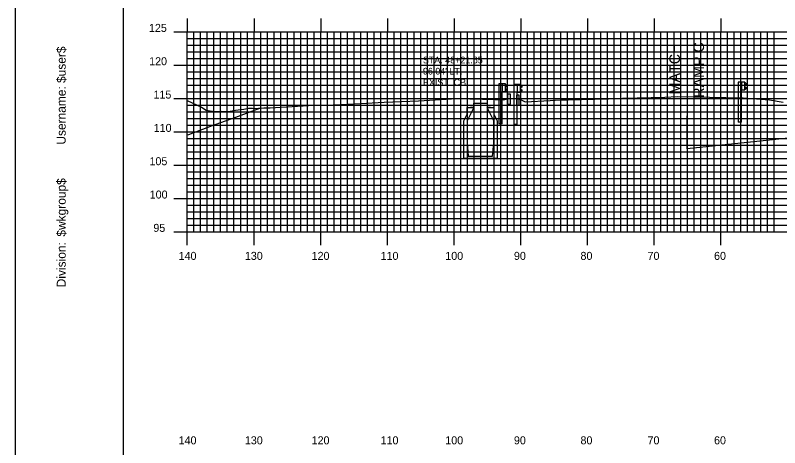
# Model space of a CAD drawing. Extents: x 1754708 to 1755051, y 442591 to 442811.
# Drawn here: x 1754707.7 to 1754822.3, y 442654.9 to 442719.8 of the extents above; entities that cross this region are included whole.
import ezdxf

# ---------------------------------------------------------------- set-up
doc = ezdxf.new("R2010")
doc.units = 0
for name, color, linetype in [('ANNOTATION', 7, 'Continuous'), ('BORDER', 7, 'Continuous'), ('D_Roadway_SlopeLines', 7, 'Continuous'), ('D_Roadway_SubGrade', 7, 'Continuous'), ('D_Text_Monospaced', 7, 'Continuous'), ('H_V ANNOTATION', 7, 'Continuous'), ('M_Roadway_Centerline', 7, 'Continuous'), ('MAJOR', 7, 'Continuous'), ('MINOR', 7, 'Continuous'), ('PLOT BOUNDARY', 7, 'Continuous'), ('S_Curb_Type_1', 7, 'Continuous'), ('S_Drainage_CB', 7, 'Continuous'), ('S_Guardrail_Beam', 7, 'Continuous'), ('S_Roadway_Centerline', 7, 'Continuous')]:
    doc.layers.add(name, color=color, linetype=linetype)

msp = doc.modelspace()

# ---------------------------------------------------------------- linework, layer by layer
at = {"layer": 'BORDER'}
msp.add_lwpolyline([(1754723.92, 442596.67), (1755043.92, 442596.67), (1755043.92, 442806.67), (1754723.92, 442806.67)], close=True, dxfattribs=at)
at = {"layer": 'D_Roadway_SlopeLines'}
for p, q in [((1754808.44, 442699.79), (1754808.44, 442704.73)), ((1754839.49, 442702.99), (1754808.44, 442699.79))]:
    msp.add_line(p, q, dxfattribs=at)
at = {"layer": 'D_Roadway_SubGrade'}
msp.add_line((1754808.44, 442716.86), (1754808.44, 442699.79), dxfattribs=at)
at = {"layer": 'MAJOR'}
for p, q in [((1754733.52, 442719.32), (1754733.52, 442717.31)), ((1754743.52, 442719.32), (1754743.52, 442717.31)), ((1754753.52, 442719.32), (1754753.52, 442717.31)), ((1754763.52, 442719.32), (1754763.52, 442717.31)), ((1754773.52, 442719.32), (1754773.52, 442717.31)), ((1754783.52, 442719.32), (1754783.52, 442717.31)), ((1754793.52, 442719.32), (1754793.52, 442717.31)), ((1754803.52, 442719.32), (1754803.52, 442717.31)), ((1754813.52, 442719.32), (1754813.52, 442717.31)), ((1754731.51, 442717.31), (1754733.52, 442717.31)), ((1754733.52, 442717.31), (1755013.52, 442717.31)), ((1754733.52, 442687.31), (1754733.52, 442717.31)), ((1754733.52, 442687.31), (1754733.52, 442717.31)), ((1754733.52, 442717.31), (1755013.52, 442717.31)), ((1754743.52, 442687.31), (1754743.52, 442717.31)), ((1754753.52, 442687.31), (1754753.52, 442717.31)), ((1754763.52, 442687.31), (1754763.52, 442717.31)), ((1754773.52, 442687.31), (1754773.52, 442717.31)), ((1754783.52, 442687.31), (1754783.52, 442717.31)), ((1754793.52, 442687.31), (1754793.52, 442717.31)), ((1754803.52, 442687.31), (1754803.52, 442717.31)), ((1754813.52, 442687.31), (1754813.52, 442717.31)), ((1754731.51, 442712.31), (1754733.52, 442712.31)), ((1754733.52, 442712.31), (1755013.52, 442712.31)), ((1754731.51, 442707.31), (1754733.52, 442707.31)), ((1754733.52, 442707.31), (1755013.52, 442707.31)), ((1754731.51, 442702.31), (1754733.52, 442702.31)), ((1754733.52, 442702.31), (1755013.52, 442702.31)), ((1754731.51, 442697.31), (1754733.52, 442697.31)), ((1754733.52, 442697.31), (1755013.52, 442697.31)), ((1754731.51, 442692.31), (1754733.52, 442692.31)), ((1754733.52, 442692.31), (1755013.52, 442692.31)), ((1754731.51, 442687.31), (1754733.52, 442687.31)), ((1754733.52, 442687.31), (1755013.52, 442687.31)), ((1754733.52, 442687.31), (1755013.52, 442687.31)), ((1754733.52, 442685.31), (1754733.52, 442687.31)), ((1754743.52, 442685.31), (1754743.52, 442687.31)), ((1754753.52, 442685.31), (1754753.52, 442687.31)), ((1754763.52, 442685.31), (1754763.52, 442687.31)), ((1754773.52, 442685.31), (1754773.52, 442687.31)), ((1754783.52, 442685.31), (1754783.52, 442687.31)), ((1754793.52, 442685.31), (1754793.52, 442687.31)), ((1754803.52, 442685.31), (1754803.52, 442687.31)), ((1754813.52, 442685.31), (1754813.52, 442687.31))]:
    msp.add_line(p, q, dxfattribs=at)
at = {"layer": 'MINOR'}
for p, q in [((1754734.52, 442687.31), (1754734.52, 442717.31)), ((1754735.52, 442687.31), (1754735.52, 442717.31)), ((1754736.52, 442687.31), (1754736.52, 442717.31)), ((1754737.52, 442687.31), (1754737.52, 442717.31)), ((1754738.52, 442687.31), (1754738.52, 442717.31)), ((1754739.52, 442687.31), (1754739.52, 442717.31)), ((1754740.52, 442687.31), (1754740.52, 442717.31)), ((1754741.52, 442687.31), (1754741.52, 442717.31)), ((1754742.52, 442687.31), (1754742.52, 442717.31)), ((1754744.52, 442687.31), (1754744.52, 442717.31)), ((1754745.52, 442687.31), (1754745.52, 442717.31)), ((1754746.52, 442687.31), (1754746.52, 442717.31)), ((1754747.52, 442687.31), (1754747.52, 442717.31)), ((1754748.52, 442687.31), (1754748.52, 442717.31)), ((1754749.52, 442687.31), (1754749.52, 442717.31)), ((1754750.52, 442687.31), (1754750.52, 442717.31)), ((1754751.52, 442687.31), (1754751.52, 442717.31)), ((1754752.52, 442687.31), (1754752.52, 442717.31)), ((1754754.52, 442687.31), (1754754.52, 442717.31)), ((1754755.52, 442687.31), (1754755.52, 442717.31)), ((1754756.52, 442687.31), (1754756.52, 442717.31)), ((1754757.52, 442687.31), (1754757.52, 442717.31)), ((1754758.52, 442687.31), (1754758.52, 442717.31)), ((1754759.52, 442687.31), (1754759.52, 442717.31)), ((1754760.52, 442687.31), (1754760.52, 442717.31)), ((1754761.52, 442687.31), (1754761.52, 442717.31)), ((1754762.52, 442687.31), (1754762.52, 442717.31)), ((1754764.52, 442687.31), (1754764.52, 442717.31)), ((1754765.52, 442687.31), (1754765.52, 442717.31)), ((1754766.52, 442687.31), (1754766.52, 442717.31)), ((1754767.52, 442687.31), (1754767.52, 442717.31)), ((1754768.52, 442687.31), (1754768.52, 442717.31)), ((1754769.52, 442687.31), (1754769.52, 442717.31)), ((1754770.52, 442687.31), (1754770.52, 442717.31)), ((1754771.52, 442687.31), (1754771.52, 442717.31)), ((1754772.52, 442687.31), (1754772.52, 442717.31)), ((1754774.52, 442687.31), (1754774.52, 442717.31)), ((1754775.52, 442687.31), (1754775.52, 442717.31)), ((1754776.52, 442687.31), (1754776.52, 442717.31)), ((1754777.52, 442687.31), (1754777.52, 442717.31)), ((1754778.52, 442687.31), (1754778.52, 442717.31)), ((1754779.52, 442687.31), (1754779.52, 442717.31)), ((1754780.52, 442687.31), (1754780.52, 442717.31)), ((1754781.52, 442687.31), (1754781.52, 442717.31)), ((1754782.52, 442687.31), (1754782.52, 442717.31)), ((1754784.52, 442687.31), (1754784.52, 442717.31)), ((1754785.52, 442687.31), (1754785.52, 442717.31)), ((1754786.52, 442687.31), (1754786.52, 442717.31)), ((1754787.52, 442687.31), (1754787.52, 442717.31)), ((1754788.52, 442687.31), (1754788.52, 442717.31)), ((1754789.52, 442687.31), (1754789.52, 442717.31)), ((1754790.52, 442687.31), (1754790.52, 442717.31)), ((1754791.52, 442687.31), (1754791.52, 442717.31)), ((1754792.52, 442687.31), (1754792.52, 442717.31)), ((1754794.52, 442687.31), (1754794.52, 442717.31)), ((1754795.52, 442687.31), (1754795.52, 442717.31)), ((1754796.52, 442687.31), (1754796.52, 442717.31)), ((1754797.52, 442687.31), (1754797.52, 442717.31)), ((1754798.52, 442687.31), (1754798.52, 442717.31)), ((1754799.52, 442687.31), (1754799.52, 442717.31)), ((1754800.52, 442687.31), (1754800.52, 442717.31)), ((1754801.52, 442687.31), (1754801.52, 442717.31)), ((1754802.52, 442687.31), (1754802.52, 442717.31)), ((1754804.52, 442687.31), (1754804.52, 442717.31)), ((1754805.52, 442687.31), (1754805.52, 442717.31)), ((1754806.52, 442687.31), (1754806.52, 442717.31)), ((1754807.52, 442687.31), (1754807.52, 442717.31)), ((1754808.52, 442687.31), (1754808.52, 442717.31)), ((1754809.52, 442687.31), (1754809.52, 442717.31)), ((1754810.52, 442687.31), (1754810.52, 442717.31)), ((1754811.52, 442687.31), (1754811.52, 442717.31)), ((1754812.52, 442687.31), (1754812.52, 442717.31)), ((1754814.52, 442687.31), (1754814.52, 442717.31)), ((1754815.52, 442687.31), (1754815.52, 442717.31)), ((1754816.52, 442687.31), (1754816.52, 442717.31)), ((1754817.52, 442687.31), (1754817.52, 442717.31)), ((1754818.52, 442687.31), (1754818.52, 442717.31)), ((1754819.52, 442687.31), (1754819.52, 442717.31)), ((1754820.52, 442687.31), (1754820.52, 442717.31)), ((1754821.52, 442687.31), (1754821.52, 442717.31)), ((1754733.52, 442716.31), (1755013.52, 442716.31)), ((1754733.52, 442716.31), (1754735.52, 442716.31)), ((1754733.52, 442715.31), (1755013.52, 442715.31)), ((1754733.52, 442715.31), (1754735.52, 442715.31)), ((1754733.52, 442714.31), (1755013.52, 442714.31)), ((1754733.52, 442714.31), (1754735.52, 442714.31)), ((1754733.52, 442713.31), (1755013.52, 442713.31)), ((1754733.52, 442713.31), (1754735.52, 442713.31)), ((1754733.52, 442711.31), (1755013.52, 442711.31)), ((1754733.52, 442711.31), (1754735.52, 442711.31)), ((1754733.52, 442710.31), (1755013.52, 442710.31)), ((1754733.52, 442710.31), (1754735.52, 442710.31)), ((1754733.52, 442709.31), (1755013.52, 442709.31)), ((1754733.52, 442709.31), (1754735.52, 442709.31)), ((1754733.52, 442708.31), (1755013.52, 442708.31)), ((1754733.52, 442708.31), (1754735.52, 442708.31)), ((1754733.52, 442706.31), (1755013.52, 442706.31)), ((1754733.52, 442706.31), (1754735.52, 442706.31)), ((1754733.52, 442705.31), (1755013.52, 442705.31)), ((1754733.52, 442705.31), (1754735.52, 442705.31)), ((1754733.52, 442704.31), (1755013.52, 442704.31)), ((1754733.52, 442704.31), (1754735.52, 442704.31)), ((1754733.52, 442703.31), (1755013.52, 442703.31)), ((1754733.52, 442703.31), (1754735.52, 442703.31)), ((1754733.52, 442701.31), (1755013.52, 442701.31)), ((1754733.52, 442701.31), (1754735.52, 442701.31)), ((1754733.52, 442700.31), (1755013.52, 442700.31)), ((1754733.52, 442700.31), (1754735.52, 442700.31)), ((1754733.52, 442699.31), (1755013.52, 442699.31)), ((1754733.52, 442699.31), (1754735.52, 442699.31)), ((1754733.52, 442698.31), (1755013.52, 442698.31)), ((1754733.52, 442698.31), (1754735.52, 442698.31)), ((1754733.52, 442696.31), (1755013.52, 442696.31)), ((1754733.52, 442696.31), (1754735.52, 442696.31)), ((1754733.52, 442695.31), (1755013.52, 442695.31)), ((1754733.52, 442695.31), (1754735.52, 442695.31)), ((1754733.52, 442694.31), (1755013.52, 442694.31)), ((1754733.52, 442694.31), (1754735.52, 442694.31)), ((1754733.52, 442693.31), (1755013.52, 442693.31)), ((1754733.52, 442693.31), (1754735.52, 442693.31)), ((1754733.52, 442691.31), (1755013.52, 442691.31)), ((1754733.52, 442691.31), (1754735.52, 442691.31)), ((1754733.52, 442690.31), (1755013.52, 442690.31)), ((1754733.52, 442690.31), (1754735.52, 442690.31)), ((1754733.52, 442689.31), (1755013.52, 442689.31)), ((1754733.52, 442689.31), (1754735.52, 442689.31)), ((1754733.52, 442688.31), (1755013.52, 442688.31)), ((1754733.52, 442688.31), (1754735.52, 442688.31))]:
    msp.add_line(p, q, dxfattribs=at)
at = {"layer": 'PLOT BOUNDARY'}
msp.add_lwpolyline([(1754707.73, 442590.55), (1755047.73, 442590.55), (1755047.73, 442810.55), (1754707.73, 442810.55)], close=True, dxfattribs=at)
at = {"layer": 'S_Curb_Type_1'}
for points in [[(1754781.96, 442707.96), (1754781.54, 442707.96), (1754781.54, 442706.46), (1754781.96, 442706.46)], [(1754783.27, 442707.81), (1754782.85, 442707.81), (1754782.85, 442706.31), (1754783.27, 442706.31)]]:
    msp.add_lwpolyline(points, close=True, dxfattribs=at)
at = {"layer": 'S_Drainage_CB'}
for p, q in [((1754775.46, 442704.98), (1754775.46, 442705.97)), ((1754775.46, 442705.97), (1754776.48, 442705.97)), ((1754776.48, 442705.97), (1754775.46, 442703.97)), ((1754778.48, 442705.97), (1754779.46, 442705.97)), ((1754779.46, 442703.97), (1754778.48, 442705.97)), ((1754779.46, 442705.97), (1754779.46, 442704.98)), ((1754774.97, 442703.97), (1754775.46, 442704.98)), ((1754779.46, 442704.98), (1754779.96, 442703.97)), ((1754774.97, 442698.32), (1754774.97, 442703.97)), ((1754775.46, 442703.97), (1754775.46, 442700.65)), ((1754779.46, 442700.65), (1754779.46, 442703.97)), ((1754779.96, 442703.97), (1754779.96, 442698.32)), ((1754775.46, 442700.65), (1754775.63, 442698.65)), ((1754779.3, 442698.65), (1754779.46, 442700.65)), ((1754779.96, 442698.32), (1754774.97, 442698.32)), ((1754775.63, 442698.65), (1754779.3, 442698.65))]:
    msp.add_line(p, q, dxfattribs=at)
msp.add_lwpolyline([(1754775.99, 442706.01), (1754776.48, 442706.01), (1754776.48, 442706.63), (1754778.48, 442706.63), (1754778.48, 442706.01), (1754778.97, 442706.01)], dxfattribs=at)
at = {"layer": 'S_Guardrail_Beam'}
for p, q in [((1754780.22, 442709.51), (1754780.22, 442703.51)), ((1754780.71, 442709.51), (1754780.22, 442709.51)), ((1754781.2, 442709.51), (1754780.71, 442709.51)), ((1754780.71, 442709.51), (1754780.71, 442708.35)), ((1754781.2, 442708.35), (1754781.2, 442709.51)), ((1754781.2, 442709.44), (1754781.28, 442709.43)), ((1754781.3, 442709.42), (1754781.44, 442709.32)), ((1754782.47, 442709.42), (1754782.47, 442703.42)), ((1754782.97, 442709.42), (1754782.47, 442709.42)), ((1754783.46, 442709.42), (1754782.97, 442709.42)), ((1754782.97, 442709.42), (1754782.97, 442708.25)), ((1754783.46, 442708.25), (1754783.46, 442709.42)), ((1754783.46, 442709.34), (1754783.54, 442709.33)), ((1754783.55, 442709.32), (1754783.7, 442709.22)), ((1754816.11, 442709.77), (1754816.11, 442703.77)), ((1754816.6, 442709.77), (1754816.11, 442709.77)), ((1754817.09, 442709.77), (1754816.6, 442709.77)), ((1754816.6, 442709.77), (1754816.6, 442708.6)), ((1754817.09, 442708.6), (1754817.09, 442709.77)), ((1754817.09, 442709.69), (1754817.17, 442709.68)), ((1754817.1, 442709.23), (1754817.1, 442709.14)), ((1754817.33, 442709.43), (1754817.13, 442709.29)), ((1754817.19, 442709.67), (1754817.33, 442709.57)), ((1754780.71, 442703.51), (1754780.71, 442708.35)), ((1754780.71, 442708.35), (1754781.2, 442708.35)), ((1754781.28, 442708.43), (1754781.2, 442708.42)), ((1754781.21, 442708.98), (1754781.21, 442708.88)), ((1754781.44, 442709.18), (1754781.24, 442709.04)), ((1754781.24, 442708.82), (1754781.44, 442708.68)), ((1754781.44, 442708.54), (1754781.3, 442708.44)), ((1754782.97, 442703.42), (1754782.97, 442708.25)), ((1754782.97, 442708.25), (1754783.46, 442708.25)), ((1754783.54, 442708.34), (1754783.46, 442708.32)), ((1754783.47, 442708.88), (1754783.47, 442708.79)), ((1754783.7, 442709.08), (1754783.5, 442708.94)), ((1754783.5, 442708.72), (1754783.7, 442708.59)), ((1754783.7, 442708.44), (1754783.55, 442708.34)), ((1754816.6, 442703.77), (1754816.6, 442708.6)), ((1754816.6, 442708.6), (1754817.09, 442708.6)), ((1754817.17, 442708.69), (1754817.09, 442708.67)), ((1754817.13, 442709.07), (1754817.33, 442708.94)), ((1754817.33, 442708.8), (1754817.19, 442708.7)), ((1754780.71, 442703.51), (1754780.22, 442703.51)), ((1754816.6, 442703.77), (1754816.11, 442703.77)), ((1754782.97, 442703.42), (1754782.47, 442703.42))]:
    msp.add_line(p, q, dxfattribs=at)
for centre, major_axis, start_param, end_param in [((1754781.27, 442709.38), (0.0417, 0), 0.959931, 1.396263), ((1754781.39, 442709.25), (0.0877, 0), 5.323254, 7.243116), ((1754783.53, 442709.29), (0.0417, 0), 0.959931, 1.396263), ((1754817.18, 442709.23), (-0.0789, 0), 5.323254, 6.283185), ((1754817.16, 442709.64), (0.0417, 0), 0.959931, 1.396263), ((1754817.28, 442709.5), (0.0877, 0), 5.323254, 7.243116), ((1754781.29, 442708.98), (-0.0789, 0), 5.323254, 6.283185), ((1754781.29, 442708.88), (-0.0789, 0), 6.283185, 7.243116), ((1754781.27, 442708.47), (0.0417, 0), 4.886922, 5.323254), ((1754781.39, 442708.61), (0.0877, 0), 5.323254, 7.243116), ((1754783.55, 442708.88), (-0.0789, 0), 5.323254, 6.283185), ((1754783.55, 442708.79), (-0.0789, 0), 6.283185, 7.243116), ((1754783.53, 442708.38), (0.0417, 0), 4.886922, 5.323254), ((1754783.65, 442709.15), (0.0877, 0), 5.323254, 7.243116), ((1754783.65, 442708.52), (0.0877, 0), 5.323254, 7.243116), ((1754817.18, 442709.14), (-0.0789, 0), 6.283185, 7.243116), ((1754817.16, 442708.73), (0.0417, 0), 4.886922, 5.323254), ((1754817.28, 442708.87), (0.0877, 0), 5.323254, 7.243116)]:
    msp.add_ellipse(centre, major_axis=major_axis, ratio=0.995501, start_param=start_param, end_param=end_param, dxfattribs=at)
at = {"layer": 'S_Roadway_Centerline'}
for points in [[(1754733.52, 442707.01), (1754735.64, 442706.01), (1754736.35, 442705.59), (1754737.61, 442705.36), (1754738.72, 442705.42), (1754739.68, 442705.39), (1754740.75, 442705.57), (1754741.97, 442705.73), (1754742.7, 442705.85), (1754743.23, 442705.86), (1754743.41, 442705.82), (1754744.97, 442705.91), (1754745.92, 442705.93), (1754751.67, 442706.25), (1754754.36, 442706.33), (1754758.57, 442706.53), (1754763.05, 442706.79), (1754765.63, 442706.88), (1754768.19, 442706.97), (1754772.35, 442707.22), (1754774, 442707.33), (1754779.68, 442707.16), (1754779.77, 442707.16), (1754780.97, 442707.12), (1754781.31, 442707.22), (1754781.96, 442707.38), (1754782.48, 442707.34), (1754783.27, 442707.23), (1754783.55, 442707.11), (1754784.15, 442706.84), (1754787.9, 442707.04), (1754789.4, 442707.12), (1754790.61, 442707.12), (1754798.65, 442707.34), (1754798.82, 442707.35), (1754798.93, 442707.35), (1754805.1, 442707.51), (1754806.96, 442707.61), (1754814.26, 442707.47), (1754816.34, 442707.43), (1754816.87, 442707.4), (1754820.81, 442707.13), (1754822.85, 442706.77)], [(1754733.52, 442701.85), (1754733.73, 442701.92), (1754736.52, 442702.96), (1754737.86, 442703.46), (1754740.78, 442704.53), (1754744.37, 442705.85)]]:
    msp.add_lwpolyline(points, dxfattribs=at)

# ---------------------------------------------------------------- texts
at = {"layer": 'ANNOTATION'}
for s, p in [('MATCH', (1754807.39, 442707.94)), ('RAMP C', (1754810.99, 442707.43))]:
    msp.add_text(s, height=1.6, rotation=90, dxfattribs=at).set_placement(p)
at = {"layer": 'BORDER'}
for s, p in [('$user$', (1754715.29, 442709.65)), ('$user$', (1754715.29, 442709.65)), ('Username:', (1754715.29, 442700.4)), ('Username:', (1754715.29, 442700.4)), ('$wkgroup$', (1754715.29, 442686.6)), ('$wkgroup$', (1754715.29, 442686.6)), ('Division:', (1754715.29, 442679)), ('Division:', (1754715.29, 442679))]:
    msp.add_text(s, height=1.339, rotation=90, dxfattribs=at).set_placement(p)
at = {"layer": 'D_Text_Monospaced'}
for s, p in [('STA. 48+21.65', (1754768.85, 442712.59)), ("96.04' LT.", (1754768.85, 442710.92)), ('EXIST. CB', (1754768.85, 442709.24))]:
    msp.add_text(s, height=1, dxfattribs=at).set_placement(p)
at = {"layer": 'H_V ANNOTATION'}
for s, p in [('125', (1754727.77, 442717.31)), ('120', (1754727.8, 442712.31)), ('115', (1754728.45, 442707.31)), ('110', (1754728.48, 442702.31)), ('105', (1754727.85, 442697.31)), ('100', (1754727.88, 442692.31)), ('95', (1754728.43, 442687.31)), ('140', (1754732.22, 442683.11)), ('130', (1754742.15, 442683.11)), ('120', (1754752.16, 442683.11)), ('110', (1754762.5, 442683.11)), ('100', (1754772.2, 442683.11)), ('90', (1754782.49, 442683.11)), ('80', (1754792.47, 442683.11)), ('70', (1754802.52, 442683.11)), ('60', (1754812.49, 442683.11)), ('140', (1754732.22, 442655.44)), ('130', (1754742.15, 442655.44)), ('120', (1754752.16, 442655.44)), ('110', (1754762.5, 442655.44)), ('100', (1754772.2, 442655.44)), ('90', (1754782.49, 442655.44)), ('80', (1754792.47, 442655.44)), ('70', (1754802.52, 442655.44)), ('60', (1754812.49, 442655.44))]:
    msp.add_text(s, height=1.2, dxfattribs=at).set_placement(p)
at = {"layer": 'M_Roadway_Centerline'}
for s, p in [('C', (1754798.81, 442707.35)), ('L', (1754798.81, 442707.34)), ('C', (1754763.05, 442706.79)), ('L', (1754763.05, 442706.78))]:
    msp.add_text(s, height=0.0146, dxfattribs=at).set_placement(p)
at = {"layer": 'MAJOR'}
msp.add_text('-', height=0.012, dxfattribs=at).set_placement((1754733.51, 442687.31))

doc.saveas('drawing.dxf')
